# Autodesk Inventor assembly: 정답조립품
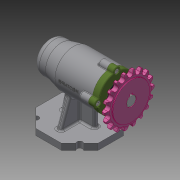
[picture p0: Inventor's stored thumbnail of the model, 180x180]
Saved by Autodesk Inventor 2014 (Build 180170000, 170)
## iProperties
Created: 2021-01
Part Number: 정답조립품
Document SubType Name: Assembly
Designer: kh
Author: kh
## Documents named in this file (12)
- C:\Users\kh\Desktop\710106V1013\정답조립품.iam
- C:\Users\kh\Desktop\710106V1013\본체.ipt
- C:\Users\kh\Desktop\710106V1013\멈춤나사 M3.ipt
- C:\Users\kh\Desktop\710106V1013\베어링 6004.ipt
- C:\Users\kh\Desktop\710106V1013\베어링 51202.ipt
- C:\Users\kh\Desktop\710106V1013\볼트 M4.ipt
- C:\Users\kh\Desktop\710106V1013\스프로킷.ipt
- C:\Users\kh\Desktop\710106V1013\어댑터슬리브.ipt
- C:\Users\kh\Desktop\710106V1013\오일 실.ipt
- C:\Users\kh\Desktop\710106V1013\축.ipt
- C:\Users\kh\Desktop\710106V1013\커버.ipt
- C:\Users\kh\Desktop\710106V1013\키 5 x 5 x 14.ipt
